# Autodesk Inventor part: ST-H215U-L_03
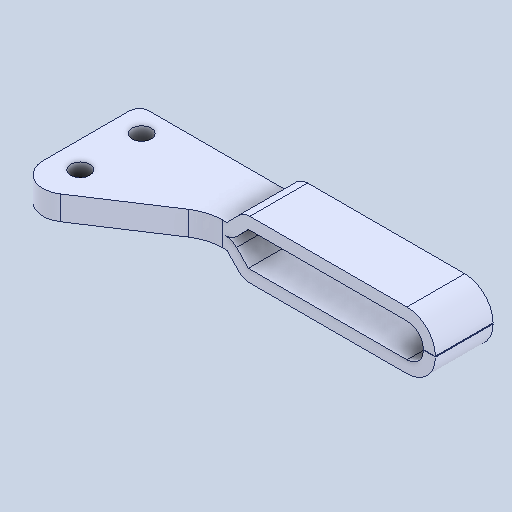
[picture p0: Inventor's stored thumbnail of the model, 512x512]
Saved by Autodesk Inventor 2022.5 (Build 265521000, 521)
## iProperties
Created: 2024-07
Part Number: ST-H215U-L_03
Material: 一般
Document SubType Name: Modeling
Designer: ImaoCorp
Density: 1 g/cm^3
Appearance: 既定
Author: ImaoCorp
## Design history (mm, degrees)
feature "ST-H215U-L_03"
node "ソリッド1"
